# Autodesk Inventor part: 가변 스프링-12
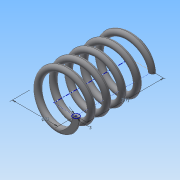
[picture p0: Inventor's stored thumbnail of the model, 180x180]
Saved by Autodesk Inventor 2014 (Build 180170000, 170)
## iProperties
Created: 2015-09
Part Number: 가변 스프링-12
Material: 강철, 탄소
Document SubType Name: Modeling
Designer: study
Density: 1 g/cm^3
Appearance: 반연마
Mass: 2.38851 g
Surface Area: 32.4648 cm^2
Volume: 2.38851 cm^3
Author: study
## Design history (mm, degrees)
sketch "스케치1"
  geometry: L1 (0, 0)-(11, 0); L2 (11, 0)-(11, 36.411); L3 (11, 36.411)-(0, 36.411); L4 (0, 36.411)-(0, 0); C1 r 1.5 at (11, 0)
  constraints: 8 end point, 2 parallel, 1 centre point, 1 coincident, 1 horizontal, 1 perpendicular
  dimensions: "d0" = 36.4112 distance of L1.end L2.end (derived); "d1" = 22 diameter of L1.end L4; "d2" = 3 diameter of C1
feature "코일1" sketch "스케치1" pitch "d3" = 10; turns "d5" = 5; dims "d4" = 36.4112 (= d0), "d6" = 0, angle "d7" = 90 deg, angle "d8" = 90 deg, "d9" = 0, "d10" = 0
node "작업 평면1"
sketch "스케치2"
  geometry: L1 (-12.5, 0)-(-9.5, 0) reference; 1 further point
  constraints: 1 horizontal alignment
extrude "돌출1" cut sketch "스케치2" stored distance "d12" = 10; taper "d13" = 0 deg
node "작업 평면2"
sketch "스케치3"
  geometry: L1 (-9.5, 0)-(-12.5, 0) reference; 1 further point
  constraints: 1 horizontal alignment
extrude "돌출2" cut sketch "스케치3" stored distance "d15" = 10; taper "d16" = 0 deg
node "솔리드1"
node "절단 모서리 투영1"
node "절단 모서리 투영2"
other parameters: "d11" = 0, "d14" = 36.4112 (= d0)
